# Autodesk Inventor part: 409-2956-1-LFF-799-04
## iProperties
Created: 2010-11
Part Number: 409-2956-1-LFF-799-04
Material: 3/4" OD TUBE - SS
Document SubType Name: Modeling
Designer: S. Boerckel
Engineer: Steve Boerckel
Mass: 731.966 g
Surface Area: 1099.2 cm^2
Volume: 90.5898 cm^3
Density: 8.08 g/cm^3
Description: DRAIN TUBING
Length: 39.238 in
Author: S. Boerckel
Revision Number: 0
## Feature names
1. Sweep2
